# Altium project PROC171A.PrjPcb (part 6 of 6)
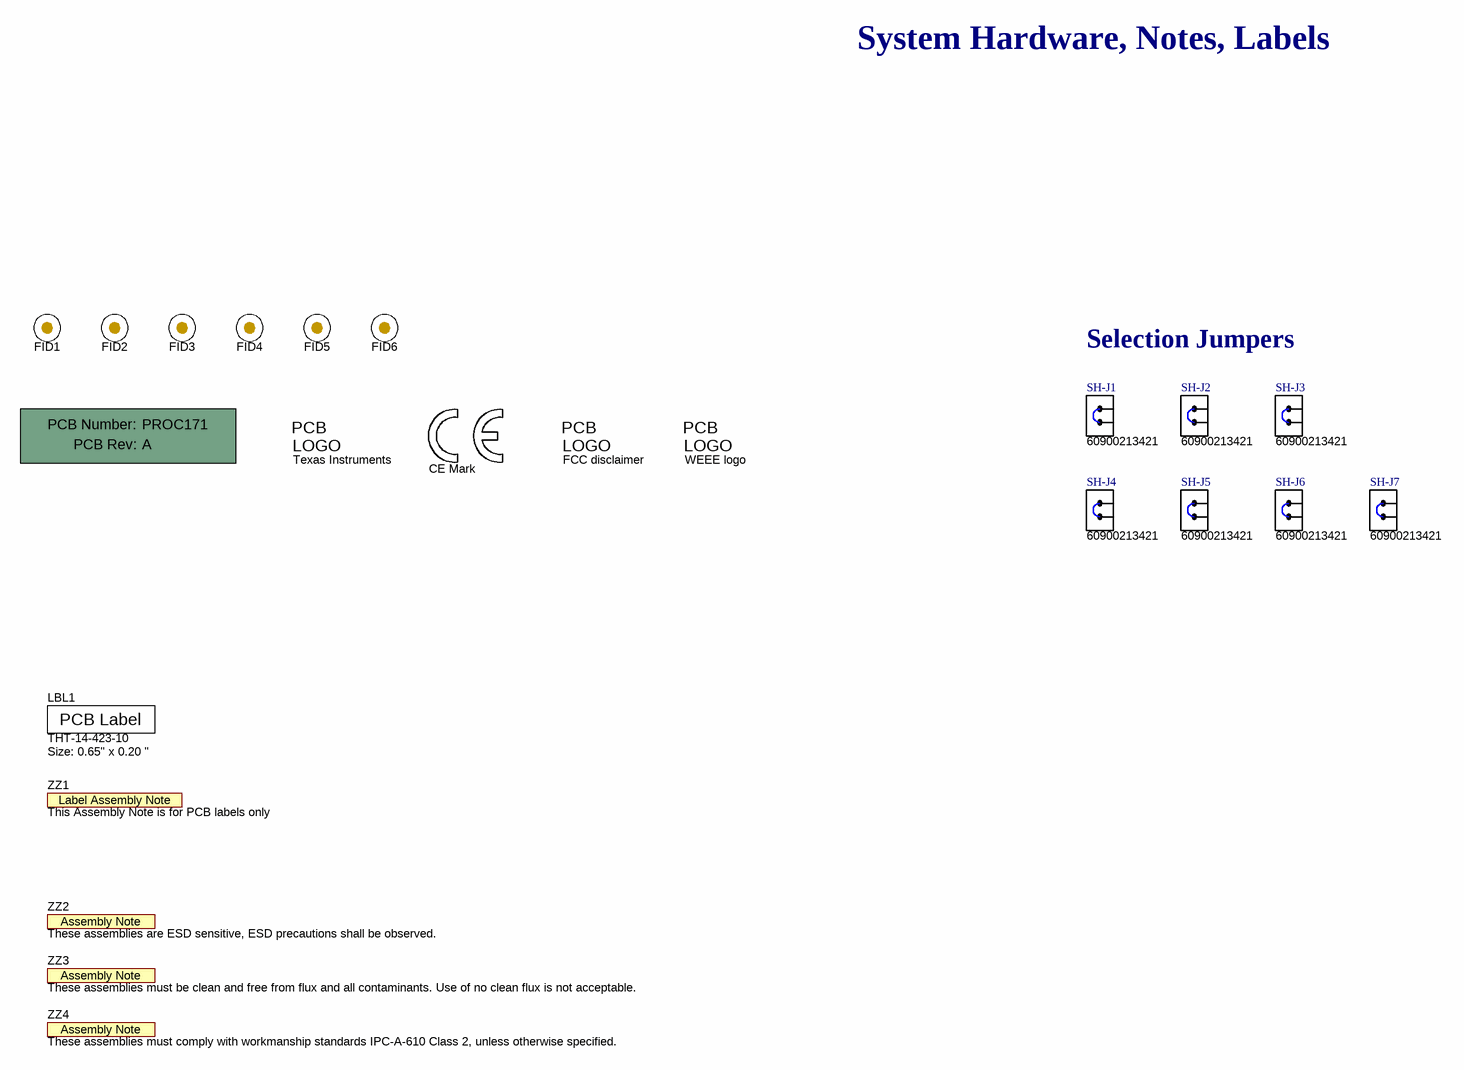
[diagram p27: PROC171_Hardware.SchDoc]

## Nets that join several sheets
GND: PROC171_System_Power_1 (34 pins), PROC171_System_Power_2 (52 pins), PROC171_AM263P_1_Power (148 pins), PROC171_AM263P_2_Clock_Reset_Boot_JTAG (30 pins), PROC171_AM263P_3_OSPI_MMC (30 pins), PROC171_AM263P_4_EMMC (17 pins), PROC171_AM263P_5_ADC_DAC (45 pins), PROC171_AM263P_6_ePWM_eQEP_FSI (6 pins), PROC171_AM263P_7_RGMII_MII (C100.1 U17.3), PROC171_AM263P_8_PRU (11 pins), PROC171_Push_Buttons (13 pins), PROC171_Test_Automation (26 pins), PROC171_Ehernet_PHY_1 (43 pins), PROC171_Ehernet_PHY_2 (37 pins), PROC171_Ehernet_RJ45_1 (10 pins), PROC171_XDS110_2 (7 pins), PROC171_Ehernet_RJ45_2 (10 pins), PROC171_Boosterpack_Headers (13 pins), PROC171_Breakout_Headers (31 pins), PROC171_IO_EXPANDER (5 pins), PROC171_LED (14 pins)
GND_XDS: PROC171_Test_Automation (7 pins), PROC171_XDS110_2 (44 pins), PROC171_XDS110_1 (14 pins)
VBUS_XDS_5V0: PROC171_XDS110_2 (R132.2 R136.2), PROC171_XDS110_1 (7 pins)
VDD_AM263P_1V2: PROC171_System_Power_2 (7 pins), PROC171_AM263P_1_Power (49 pins)
VDD_ETH_1V1: PROC171_System_Power_2 (6 pins), PROC171_Ehernet_PHY_1 (FB3.1), PROC171_Ehernet_PHY_2 (FB5.1)
VDD_ETH_2V5: PROC171_System_Power_2 (6 pins), PROC171_Ehernet_PHY_1 (FB4.1), PROC171_Ehernet_PHY_2 (FB6.1)
VDD_XDS3V3: PROC171_Test_Automation (13 pins), PROC171_XDS110_2 (38 pins), PROC171_XDS110_1 (7 pins)
VDDA_AM263P_1V8_LDO: PROC171_AM263P_1_Power (10 pins), PROC171_AM263P_5_ADC_DAC (S1.1)
VPP_AM263P_1V7: PROC171_System_Power_2 (5 pins), PROC171_AM263P_1_Power (R190.2 R360.2)
VSYS_3V3: PROC171_System_Power_1 (J12.1), PROC171_System_Power_2 (14 pins), PROC171_AM263P_1_Power (19 pins), PROC171_AM263P_2_Clock_Reset_Boot_JTAG (14 pins), PROC171_AM263P_Serial_Connectivity (R175.2 R176.2), PROC171_AM263P_3_OSPI_MMC (38 pins), PROC171_AM263P_4_EMMC (15 pins), PROC171_AM263P_6_ePWM_eQEP_FSI (7 pins), PROC171_AM263P_7_RGMII_MII (C100.2 R63.2 R64.2 U17.8), PROC171_AM263P_8_PRU (14 pins), PROC171_Push_Buttons (8 pins), PROC171_Test_Automation (U57.1), PROC171_Ehernet_PHY_1 (30 pins), PROC171_Ehernet_PHY_2 (22 pins), PROC171_Ehernet_RJ45_1 (R224.1 R226.2 R228.2), PROC171_XDS110_2 (6 pins), PROC171_Ehernet_RJ45_2 (R230.1 R232.2 R234.2), PROC171_Boosterpack_Headers (12 pins), PROC171_Breakout_Headers (8 pins), PROC171_IO_EXPANDER (6 pins), PROC171_LED (17 pins)
VSYS_5V0: PROC171_System_Power_1 (5 pins), PROC171_System_Power_2 (23 pins), PROC171_AM263P_1_Power (R1.2), PROC171_Breakout_Headers (16 pins), PROC171_LED (R257.2 R265.2 R302.2)
VSYS_TA_3V3: PROC171_AM263P_2_Clock_Reset_Boot_JTAG (12 pins), PROC171_Test_Automation (26 pins), PROC171_LED (R315.2)
VUSB_5V0: PROC171_System_Power_1 (20 pins), PROC171_Test_Automation (C187.2 C188.1 R193.2 U36.2), PROC171_Boosterpack_Headers (J10.1 J14.1)
ADC_EXT_VREF: PROC171_AM263P_5_ADC_DAC (S2.3 S2.6), PROC171_Breakout_Headers (J17.2)
AM263P_ADC0_AIN0: PROC171_AM263P_5_ADC_DAC (C72.1 U1.V15 U12.1 U12.10), PROC171_Boosterpack_Headers (J1/J3.23)
AM263P_ADC0_AIN1: PROC171_AM263P_5_ADC_DAC (C82.1 U1.U15 U13.2 U13.9), PROC171_Boosterpack_Headers (J1/J3.28)
AM263P_ADC0_AIN2: PROC171_AM263P_5_ADC_DAC (U1.T14), PROC171_Boosterpack_Headers (U52.32)
AM263P_ADC0_AIN2_LIN1_TXD: PROC171_AM263P_5_ADC_DAC (C88.1 U14.5 U14.6), PROC171_Boosterpack_Headers (J5/J7.66 U52.7)
AM263P_ADC0_AIN3: PROC171_AM263P_5_ADC_DAC (C84.1 U1.U14 U13.5 U13.6), PROC171_Boosterpack_Headers (J1/J3.2)
AM263P_ADC1_AIN0: PROC171_AM263P_5_ADC_DAC (C73.1 U1.T11 U12.2 U12.9), PROC171_Boosterpack_Headers (J1/J3.24)
AM263P_ADC1_AIN1: PROC171_AM263P_5_ADC_DAC (C83.1 U1.U11 U13.4 U13.7), PROC171_Boosterpack_Headers (J1/J3.29)
AM263P_ADC1_AIN2: PROC171_AM263P_5_ADC_DAC (U1.T12), PROC171_Boosterpack_Headers (U52.29)
AM263P_ADC1_AIN2_SDFM0_D2: PROC171_AM263P_5_ADC_DAC (C92.1 U15.1 U15.10), PROC171_Boosterpack_Headers (J5/J7.67 U52.11)
AM263P_ADC1_AIN3: PROC171_AM263P_5_ADC_DAC (C97.1 D16.1 U1.V12), PROC171_Boosterpack_Headers (J1/J3.6)
AM263P_ADC2_AIN0: PROC171_AM263P_5_ADC_DAC (C74.1 U1.R10 U12.4 U12.7), PROC171_Boosterpack_Headers (J1/J3.25)
AM263P_ADC2_AIN1: PROC171_AM263P_5_ADC_DAC (U1.T10), PROC171_Boosterpack_Headers (U52.38)
AM263P_ADC2_AIN1_MCAN5_RX: PROC171_AM263P_5_ADC_DAC (C85.1 U14.1 U14.10), PROC171_Boosterpack_Headers (J5/J7.63 U52.4)
AM263P_ADC2_AIN2: PROC171_AM263P_5_ADC_DAC (U1.U10), PROC171_Boosterpack_Headers (U52.27)
AM263P_ADC2_AIN2_SDFM0_CLK2: PROC171_AM263P_5_ADC_DAC (C93.1 U15.2 U15.9), PROC171_Boosterpack_Headers (J5/J7.68 U52.12)
AM263P_ADC2_AIN3: PROC171_AM263P_5_ADC_DAC (C95.1 U1.T9 U15.5 U15.6), PROC171_Boosterpack_Headers (J5/J7.42)
AM263P_ADC3_AIN0: PROC171_AM263P_5_ADC_DAC (C75.1 U1.U7 U12.5 U12.6), PROC171_Boosterpack_Headers (J1/J3.26)
AM263P_ADC3_AIN1: PROC171_AM263P_5_ADC_DAC (U1.U8), PROC171_Boosterpack_Headers (U52.36)
AM263P_ADC3_AIN1_MCAN5_TX: PROC171_AM263P_5_ADC_DAC (C86.1 U14.2 U14.9), PROC171_Boosterpack_Headers (J5/J7.64 U52.5)
AM263P_ADC3_AIN2: PROC171_AM263P_5_ADC_DAC (U1.T7), PROC171_Boosterpack_Headers (U52.25)
AM263P_ADC3_AIN2_SDFM0_D3: PROC171_AM263P_5_ADC_DAC (C94.1 U15.4 U15.7), PROC171_Boosterpack_Headers (J5/J7.69 U52.13)
AM263P_ADC3_AIN3: PROC171_AM263P_5_ADC_DAC (C96.1 D15.2 U1.R7), PROC171_Boosterpack_Headers (J5/J7.46)
AM263P_ADC4_AIN0: PROC171_AM263P_5_ADC_DAC (C81.1 U1.U6 U13.1 U13.10), PROC171_Boosterpack_Headers (J1/J3.27)
AM263P_ADC4_AIN1: PROC171_AM263P_5_ADC_DAC (U1.V5), PROC171_Boosterpack_Headers (U52.34)
AM263P_ADC4_AIN1_LIN1_RXD: PROC171_AM263P_5_ADC_DAC (C87.1 U14.4 U14.7), PROC171_Boosterpack_Headers (J5/J7.65 U52.6)
AM263P_BP_MUX_SEL: PROC171_Boosterpack_Headers (R298.2 R300.2 U51.1), PROC171_IO_EXPANDER (U63.7)
AM263P_CLKOUT0: PROC171_AM263P_2_Clock_Reset_Boot_JTAG (R4.2 TP1.1), PROC171_Ehernet_PHY_1 (R118.1)
AM263P_DAC_OUT1: PROC171_AM263P_5_ADC_DAC (R45.1), PROC171_Boosterpack_Headers (J1/J3.30)
AM263P_DAC_OUT2: PROC171_AM263P_5_ADC_DAC (R3.1), PROC171_Boosterpack_Headers (U52.23)
AM263P_EMMC0_CLK_MUX: PROC171_AM263P_3_OSPI_MMC (U53.40), PROC171_AM263P_4_EMMC (U61.M6)
AM263P_EMMC0_CMD_MUX: PROC171_AM263P_3_OSPI_MMC (U53.37), PROC171_AM263P_4_EMMC (U61.M5)
AM263P_EMMC0_D0_MUX: PROC171_AM263P_3_OSPI_MMC (U53.35), PROC171_AM263P_4_EMMC (R429.2)
AM263P_EMMC0_D1_MUX: PROC171_AM263P_3_OSPI_MMC (U53.33), PROC171_AM263P_4_EMMC (R430.2)
AM263P_EMMC0_D2_MUX: PROC171_AM263P_3_OSPI_MMC (U53.31), PROC171_AM263P_4_EMMC (R431.2)
AM263P_EMMC0_D3_MUX: PROC171_AM263P_3_OSPI_MMC (U53.28), PROC171_AM263P_4_EMMC (R432.2)
AM263P_EPWM0_A: PROC171_AM263P_6_ePWM_eQEP_FSI (R46.1), PROC171_Boosterpack_Headers (J2/J4.11)
AM263P_EPWM0_B: PROC171_AM263P_6_ePWM_eQEP_FSI (R47.1), PROC171_Boosterpack_Headers (J6/J8.59)
AM263P_EPWM1_A: PROC171_AM263P_6_ePWM_eQEP_FSI (R48.1), PROC171_Boosterpack_Headers (J2/J4.37)
AM263P_EPWM1_B: PROC171_AM263P_6_ePWM_eQEP_FSI (R49.1), PROC171_Boosterpack_Headers (J2/J4.38)
AM263P_EPWM2_A: PROC171_AM263P_6_ePWM_eQEP_FSI (R50.1), PROC171_Boosterpack_Headers (J2/J4.39)
AM263P_EPWM2_B: PROC171_AM263P_6_ePWM_eQEP_FSI (R51.1), PROC171_Boosterpack_Headers (J2/J4.40)
AM263P_EPWM3_A: PROC171_AM263P_6_ePWM_eQEP_FSI (R52.1), PROC171_Boosterpack_Headers (J6/J8.77)
AM263P_EPWM3_B: PROC171_AM263P_6_ePWM_eQEP_FSI (R53.1), PROC171_Boosterpack_Headers (J6/J8.78)
AM263P_EPWM4_A: PROC171_AM263P_6_ePWM_eQEP_FSI (R433.1), PROC171_Boosterpack_Headers (J6/J8.52)
AM263P_EPWM7_B: PROC171_AM263P_6_ePWM_eQEP_FSI (R436.1), PROC171_Boosterpack_Headers (J6/J8.51)
AM263P_EPWM9_A: PROC171_AM263P_6_ePWM_eQEP_FSI (R9.1), PROC171_Boosterpack_Headers (J6/J8.75)
AM263P_EPWM9_B: PROC171_AM263P_6_ePWM_eQEP_FSI (R12.1), PROC171_Boosterpack_Headers (J6/J8.76)
AM263P_EPWM12_A: PROC171_AM263P_6_ePWM_eQEP_FSI (R280.1), PROC171_Boosterpack_Headers (J6/J8.53)
AM263P_EPWM12_B: PROC171_AM263P_6_ePWM_eQEP_FSI (R281.1), PROC171_Boosterpack_Headers (J6/J8.57)
AM263P_EPWM13_A: PROC171_AM263P_6_ePWM_eQEP_FSI (R59.1), PROC171_Boosterpack_Headers (J6/J8.79)
AM263P_EPWM13_B: PROC171_AM263P_6_ePWM_eQEP_FSI (R60.1), PROC171_Boosterpack_Headers (J6/J8.80)
AM263P_EPWM14_A: PROC171_AM263P_6_ePWM_eQEP_FSI (R282.1), PROC171_Boosterpack_Headers (J2/J4.35)
AM263P_EPWM14_B: PROC171_AM263P_6_ePWM_eQEP_FSI (R283.1), PROC171_Boosterpack_Headers (J2/J4.36)
AM263P_EPWM15_A_BP: PROC171_AM263P_6_ePWM_eQEP_FSI (U54.3), PROC171_Boosterpack_Headers (J2/J4.34)
AM263P_EPWM15_B_BP: PROC171_AM263P_6_ePWM_eQEP_FSI (U54.6), PROC171_Boosterpack_Headers (J5/J7.45)
AM263P_EQEP0_A: PROC171_AM263P_6_ePWM_eQEP_FSI (U1.B14), PROC171_Breakout_Headers (R328.1)
AM263P_EQEP0_B: PROC171_AM263P_6_ePWM_eQEP_FSI (U1.A14), PROC171_Breakout_Headers (R329.1)
AM263P_EQEP0_INDEX: PROC171_AM263P_6_ePWM_eQEP_FSI (U1.D11), PROC171_Breakout_Headers (R330.1)
AM263P_EQEP0_STROBE: PROC171_AM263P_6_ePWM_eQEP_FSI (U1.C12), PROC171_Breakout_Headers (R331.1)
AM263P_EQEP2_A: PROC171_AM263P_Serial_Connectivity (U1.B13), PROC171_Breakout_Headers (R332.1)
AM263P_EQEP2_B: PROC171_AM263P_Serial_Connectivity (U1.A13), PROC171_Breakout_Headers (R333.1)
AM263P_EQEP2_INDEX: PROC171_AM263P_Serial_Connectivity (U1.A12), PROC171_Breakout_Headers (R334.1)
AM263P_EQEP2_STROBE: PROC171_AM263P_Serial_Connectivity (U1.B12), PROC171_Breakout_Headers (R335.1)
AM263P_FSIRX1_CLK: PROC171_AM263P_6_ePWM_eQEP_FSI (U1.E1), PROC171_Breakout_Headers (J23.1)
AM263P_FSIRX1_DATA0: PROC171_AM263P_6_ePWM_eQEP_FSI (U1.F3), PROC171_Breakout_Headers (J23.5)
AM263P_FSIRX1_DATA1: PROC171_AM263P_6_ePWM_eQEP_FSI (U1.F4), PROC171_Breakout_Headers (J23.7)
AM263P_FSITX1_CLK: PROC171_AM263P_6_ePWM_eQEP_FSI (R54.1), PROC171_Breakout_Headers (J23.2)
AM263P_FSITX1_DATA0: PROC171_AM263P_6_ePWM_eQEP_FSI (R57.1), PROC171_Breakout_Headers (J23.6)
AM263P_FSITX1_DATA1: PROC171_AM263P_6_ePWM_eQEP_FSI (R58.1), PROC171_Breakout_Headers (J23.8)
AM263P_I2C1_SCL: PROC171_AM263P_2_Clock_Reset_Boot_JTAG (U16.6), PROC171_AM263P_Serial_Connectivity (R175.1 U1.D7), PROC171_Test_Automation (U57.3), PROC171_Boosterpack_Headers (J5/J7.49), PROC171_IO_EXPANDER (U63.19), PROC171_LED (U48.15)
AM263P_I2C1_SDA: PROC171_AM263P_2_Clock_Reset_Boot_JTAG (U16.5), PROC171_AM263P_Serial_Connectivity (R176.1 U1.C8), PROC171_Test_Automation (U57.2), PROC171_Boosterpack_Headers (J5/J7.50), PROC171_IO_EXPANDER (U63.20), PROC171_LED (U48.2)
AM263P_I2C3_SCL: PROC171_AM263P_6_ePWM_eQEP_FSI (R55.1 U1.H2), PROC171_Boosterpack_Headers (J1/J3.9)
AM263P_I2C3_SDA: PROC171_AM263P_6_ePWM_eQEP_FSI (R56.1 U1.G3), PROC171_Boosterpack_Headers (J1/J3.10)
AM263P_ICSSM_MII0_COL: PROC171_AM263P_8_PRU (U49.11), PROC171_Ehernet_PHY_2 (R207.1 R219.2 U37.45), PROC171_Ehernet_RJ45_2 (R231.2)
AM263P_ICSSM_MII0_RXCLK: PROC171_AM263P_8_PRU (U23.32), PROC171_Ehernet_PHY_2 (R196.1)
AM263P_ICSSM_MII0_RXD0: PROC171_AM263P_8_PRU (U23.41), PROC171_Ehernet_PHY_2 (R198.1 R203.1 R215.2)
AM263P_ICSSM_MII0_RXD1: PROC171_AM263P_8_PRU (U23.39), PROC171_Ehernet_PHY_2 (R199.1 R204.1 R216.2)
AM263P_ICSSM_MII0_RXD2: PROC171_AM263P_8_PRU (U23.38), PROC171_Ehernet_PHY_2 (R200.1 R210.1 R222.2)
AM263P_ICSSM_MII0_RXD3: PROC171_AM263P_8_PRU (U23.36), PROC171_Ehernet_PHY_2 (R201.1 R211.1 R223.2)
AM263P_ICSSM_MII0_RXDV: PROC171_AM263P_8_PRU (U23.34), PROC171_Ehernet_PHY_2 (R197.1 R205.1 R217.2)
AM263P_ICSSM_MII0_RXER: PROC171_AM263P_8_PRU (U49.2), PROC171_Ehernet_PHY_2 (R206.1 R218.2 U37.46), PROC171_Ehernet_RJ45_2 (R235.2)
AM263P_ICSSM_MII0_RXLINK: PROC171_AM263P_8_PRU (U49.5), PROC171_Ehernet_PHY_2 (R208.1 R220.2 U37.47), PROC171_Ehernet_RJ45_2 (R233.2)
AM263P_ICSSM_MII0_TXCLK: PROC171_AM263P_8_PRU (U23.19), PROC171_Ehernet_PHY_2 (U37.29)
AM263P_ICSSM_MII0_TXD0: PROC171_AM263P_8_PRU (U23.29), PROC171_Ehernet_PHY_2 (U37.28)
AM263P_ICSSM_MII0_TXD1: PROC171_AM263P_8_PRU (U23.27), PROC171_Ehernet_PHY_2 (U37.27)
AM263P_ICSSM_MII0_TXD2: PROC171_AM263P_8_PRU (U23.25), PROC171_Ehernet_PHY_2 (U37.26)
AM263P_ICSSM_MII0_TXD3: PROC171_AM263P_8_PRU (U23.23), PROC171_Ehernet_PHY_2 (U37.25)
AM263P_ICSSM_MII0_TXEN: PROC171_AM263P_8_PRU (U23.21), PROC171_Ehernet_PHY_2 (U37.37)
AM263P_ICSSM_MII1_COL: PROC171_AM263P_8_PRU (U1.C18), PROC171_Ehernet_PHY_1 (R112.1 R124.2 U22.45), PROC171_Ehernet_RJ45_1 (R225.2)
AM263P_ICSSM_MII1_RXCLK: PROC171_AM263P_8_PRU (U1.E16), PROC171_Ehernet_PHY_1 (U50.31)
AM263P_ICSSM_MII1_RXD0: PROC171_AM263P_8_PRU (U1.F18), PROC171_Ehernet_PHY_1 (U50.42)
AM263P_ICSSM_MII1_RXD1: PROC171_AM263P_8_PRU (U1.G16), PROC171_Ehernet_PHY_1 (U50.40)
AM263P_ICSSM_MII1_RXD2: PROC171_AM263P_8_PRU (U1.E17), PROC171_Ehernet_PHY_1 (U50.37)
AM263P_ICSSM_MII1_RXD3: PROC171_AM263P_8_PRU (U1.E18), PROC171_Ehernet_PHY_1 (U50.35)
AM263P_ICSSM_MII1_RXDV: PROC171_AM263P_8_PRU (U1.F16), PROC171_Ehernet_PHY_1 (U50.33)
AM263P_ICSSM_MII1_RXER: PROC171_AM263P_8_PRU (U1.F15), PROC171_Ehernet_PHY_1 (R111.1 R123.2 U22.46), PROC171_Ehernet_RJ45_1 (R229.2)
AM263P_ICSSM_MII1_RXLINK: PROC171_AM263P_8_PRU (U1.D18), PROC171_Ehernet_PHY_1 (R110.1 R122.2 U22.47), PROC171_Ehernet_RJ45_1 (R227.2)
AM263P_ICSSM_MII1_TXCLK: PROC171_AM263P_8_PRU (R86.1), PROC171_Ehernet_PHY_1 (U50.18)
AM263P_ICSSM_MII1_TXD0: PROC171_AM263P_8_PRU (R81.1), PROC171_Ehernet_PHY_1 (U50.28)
AM263P_ICSSM_MII1_TXD1: PROC171_AM263P_8_PRU (R82.1), PROC171_Ehernet_PHY_1 (U50.26)
AM263P_ICSSM_MII1_TXD2: PROC171_AM263P_8_PRU (R83.1), PROC171_Ehernet_PHY_1 (U50.24)
AM263P_ICSSM_MII1_TXD3: PROC171_AM263P_8_PRU (R84.1), PROC171_Ehernet_PHY_1 (U50.22)
AM263P_ICSSM_MII1_TXEN: PROC171_AM263P_8_PRU (R85.1), PROC171_Ehernet_PHY_1 (U50.20)
AM263P_IEP0_EDC_SYNC_OUT0: PROC171_AM263P_8_PRU (R88.1), PROC171_Boosterpack_Headers (J6/J8.72)
AM263P_IEP0_EDIO_DATA_IN_OUT31: PROC171_AM263P_8_PRU (R87.1), PROC171_Boosterpack_Headers (J6/J8.71)
AM263P_INT1_PB_GPIO123: PROC171_AM263P_9_SDFM (U1.D14), PROC171_Push_Buttons (U34.4)
AM263P_LED_DRIVER_EN: PROC171_IO_EXPANDER (U63.5), PROC171_LED (R278.2 U48.8)
AM263P_LED_EN: PROC171_IO_EXPANDER (U63.6), PROC171_LED (R303.1 R304.2)
AM263P_LIN1_RXD: PROC171_AM263P_Serial_Connectivity (U1.A9), PROC171_Boosterpack_Headers (U52.33)
AM263P_LIN1_TXD: PROC171_AM263P_Serial_Connectivity (R297.1), PROC171_Boosterpack_Headers (U52.31)
AM263P_LIN2_RXD: PROC171_AM263P_Serial_Connectivity (U1.B8), PROC171_Boosterpack_Headers (U52.41)
AM263P_LIN2_TXD: PROC171_AM263P_Serial_Connectivity (R166.1), PROC171_Boosterpack_Headers (U52.39)
AM263P_MCAN3_RX: PROC171_AM263P_Serial_Connectivity (U1.B7), PROC171_Breakout_Headers (R249.1)
AM263P_MCAN3_TX: PROC171_AM263P_Serial_Connectivity (R401.1), PROC171_Breakout_Headers (U42.1)
AM263P_MCAN5_RX: PROC171_AM263P_6_ePWM_eQEP_FSI (U1.G4), PROC171_Boosterpack_Headers (U52.37)
AM263P_MCAN5_TX: PROC171_AM263P_6_ePWM_eQEP_FSI (R393.1), PROC171_Boosterpack_Headers (U52.35)
AM263P_MCAN_STB: PROC171_Breakout_Headers (R248.2), PROC171_IO_EXPANDER (U63.12)
AM263P_MMC_MUX_EN: PROC171_AM263P_3_OSPI_MMC (R390.2 R392.2 U53.8), PROC171_IO_EXPANDER (U63.11)
AM263P_MMC_MUX_SEL: PROC171_AM263P_3_OSPI_MMC (R389.2 R391.2 U53.9 U53.10), PROC171_IO_EXPANDER (U63.10)
AM263P_OSPI0_D4: PROC171_AM263P_Serial_Connectivity (R403.1), PROC171_AM263P_3_OSPI_MMC (R361.1 R370.2)
AM263P_OSPI0_D5: PROC171_AM263P_Serial_Connectivity (R167.1), PROC171_AM263P_3_OSPI_MMC (R365.1 R369.2)
AM263P_OSPI0_D6: PROC171_AM263P_Serial_Connectivity (R404.1), PROC171_AM263P_3_OSPI_MMC (R366.1 R368.2)
AM263P_OSPI0_D7: PROC171_AM263P_Serial_Connectivity (R168.1), PROC171_AM263P_3_OSPI_MMC (R367.2 R376.1)
AM263P_OSPI0_DQS: PROC171_AM263P_Serial_Connectivity (R165.1), PROC171_AM263P_3_OSPI_MMC (R381.1)
AM263P_OSPI0_LBCLK: PROC171_AM263P_Serial_Connectivity (R402.1), PROC171_AM263P_3_OSPI_MMC (R382.1)
AM263P_OSPI0_RST: PROC171_AM263P_3_OSPI_MMC (R387.1 U35.1), PROC171_AM263P_6_ePWM_eQEP_FSI (R99.1)
AM263P_OSPI_ECS: PROC171_AM263P_3_OSPI_MMC (R435.1 U7.A5), PROC171_AM263P_6_ePWM_eQEP_FSI (R13.1)
AM263P_PORZ_PB: PROC171_AM263P_2_Clock_Reset_Boot_JTAG (U2.1), PROC171_Push_Buttons (U34.6)
AM263P_PR0_MDIO0_MDC: PROC171_AM263P_7_RGMII_MII (U17.2), PROC171_AM263P_8_PRU (R71.1 R73.1)
AM263P_PR0_MDIO0_MDIO: PROC171_AM263P_7_RGMII_MII (U17.4), PROC171_AM263P_8_PRU (R72.1 R74.1)
AM263P_PRU/BP_MUX_EN: PROC171_AM263P_8_PRU (R288.2 R290.2 U23.8 U46.2), PROC171_Boosterpack_Headers (U52.8), PROC171_IO_EXPANDER (U63.15)
AM263P_PRU_MUX_SEL: PROC171_AM263P_8_PRU (5 pins), PROC171_IO_EXPANDER (U63.8)
AM263P_RESETN_PB: PROC171_AM263P_2_Clock_Reset_Boot_JTAG (R5.1), PROC171_Push_Buttons (R179.1 U33.4)
AM263P_RGMII1_RD0: PROC171_AM263P_7_RGMII_MII (U1.U17), PROC171_Ehernet_PHY_1 (U50.41)
AM263P_RGMII1_RD1: PROC171_AM263P_7_RGMII_MII (U1.T17), PROC171_Ehernet_PHY_1 (U50.39)
AM263P_RGMII1_RD2: PROC171_AM263P_7_RGMII_MII (U1.U18), PROC171_Ehernet_PHY_1 (U50.38)
AM263P_RGMII1_RD3: PROC171_AM263P_7_RGMII_MII (U1.T18), PROC171_Ehernet_PHY_1 (U50.36)
AM263P_RGMII1_RX_CTL: PROC171_AM263P_7_RGMII_MII (U1.R18), PROC171_Ehernet_PHY_1 (U50.34)
AM263P_RGMII1_RXC: PROC171_AM263P_7_RGMII_MII (U1.R17), PROC171_Ehernet_PHY_1 (U50.32)
AM263P_RGMII1_TD0: PROC171_AM263P_7_RGMII_MII (R65.1), PROC171_Ehernet_PHY_1 (U50.29)
AM263P_RGMII1_TD1: PROC171_AM263P_7_RGMII_MII (R66.1), PROC171_Ehernet_PHY_1 (U50.27)
AM263P_RGMII1_TD2: PROC171_AM263P_7_RGMII_MII (R67.1), PROC171_Ehernet_PHY_1 (U50.25)
AM263P_RGMII1_TD3: PROC171_AM263P_7_RGMII_MII (R68.1), PROC171_Ehernet_PHY_1 (U50.23)
AM263P_RGMII1_TX_CTL: PROC171_AM263P_7_RGMII_MII (R69.1), PROC171_Ehernet_PHY_1 (U50.21)
AM263P_RGMII1_TXC: PROC171_AM263P_7_RGMII_MII (R70.1), PROC171_Ehernet_PHY_1 (U50.19)
AM263P_SAFETY_ERRORN: PROC171_AM263P_2_Clock_Reset_Boot_JTAG (R258.1 U1.D4), PROC171_LED (R268.1 R272.1)
AM263P_SD_ENABLE_GPIO122: PROC171_AM263P_3_OSPI_MMC (U9.2), PROC171_AM263P_9_SDFM (U1.B16)
AM263P_SDFM0_CLK1: PROC171_AM263P_9_SDFM (U1.A16), PROC171_Boosterpack_Headers (J6/J8.74)
AM263P_SDFM0_CLK2: PROC171_AM263P_9_SDFM (U1.B15), PROC171_Boosterpack_Headers (U52.26)
AM263P_SDFM0_CLK3: PROC171_AM263P_9_SDFM (U1.A15), PROC171_Boosterpack_Headers (U52.22)
AM263P_SDFM0_D2: PROC171_AM263P_9_SDFM (U1.C13), PROC171_Boosterpack_Headers (U52.28)
AM263P_SDFM0_D3: PROC171_AM263P_9_SDFM (U1.C14), PROC171_Boosterpack_Headers (U52.24)
AM263P_SFDM0_D1: PROC171_AM263P_9_SDFM (U1.D13), PROC171_Boosterpack_Headers (J6/J8.73)
AM263P_SOP0: PROC171_AM263P_2_Clock_Reset_Boot_JTAG (U4.15), PROC171_AM263P_3_OSPI_MMC (R42.2)
AM263P_SOP1: PROC171_AM263P_2_Clock_Reset_Boot_JTAG (U4.14), PROC171_AM263P_3_OSPI_MMC (R43.2)
AM263P_SOP2: PROC171_AM263P_2_Clock_Reset_Boot_JTAG (U4.13), PROC171_AM263P_Serial_Connectivity (R173.2)
AM263P_SOP3: PROC171_AM263P_2_Clock_Reset_Boot_JTAG (U4.12), PROC171_AM263P_Serial_Connectivity (R174.2)
AM263P_SPI0_CLK: PROC171_AM263P_Serial_Connectivity (R169.1 R173.1), PROC171_Boosterpack_Headers (U51.2)
AM263P_SPI0_CS0: PROC171_AM263P_Serial_Connectivity (U1.C11), PROC171_Boosterpack_Headers (U51.14)
AM263P_SPI0_D0: PROC171_AM263P_Serial_Connectivity (R170.1 R174.1), PROC171_Boosterpack_Headers (U51.11)
AM263P_SPI0_D1: PROC171_AM263P_Serial_Connectivity (U1.B11), PROC171_Boosterpack_Headers (U51.5)
AM263P_SPI1_CLK: PROC171_AM263P_Serial_Connectivity (R171.1), PROC171_Boosterpack_Headers (J5/J7.47)
AM263P_SPI1_CS0: PROC171_AM263P_Serial_Connectivity (U1.C9), PROC171_Boosterpack_Headers (J6/J8.58)
AM263P_SPI1_D0: PROC171_AM263P_Serial_Connectivity (R172.1), PROC171_Boosterpack_Headers (J6/J8.55)
AM263P_SPI1_D1: PROC171_AM263P_Serial_Connectivity (U1.D9), PROC171_Boosterpack_Headers (J6/J8.54)
AM263P_TCK: PROC171_AM263P_2_Clock_Reset_Boot_JTAG (U1.B3), PROC171_XDS110_2 (R324.1)
AM263P_TDI: PROC171_AM263P_2_Clock_Reset_Boot_JTAG (U1.C5), PROC171_XDS110_2 (R326.1)
AM263P_TDO: PROC171_AM263P_2_Clock_Reset_Boot_JTAG (R7.1), PROC171_XDS110_2 (U26.3)
AM263P_TMS: PROC171_AM263P_2_Clock_Reset_Boot_JTAG (U1.D5), PROC171_XDS110_2 (R325.1)
AM263P_U52_MUX_SEL: PROC171_Boosterpack_Headers (R441.2 R442.2 U52.9 U52.10), PROC171_IO_EXPANDER (U63.16)
AM263P_UART0_RXD: PROC171_AM263P_Serial_Connectivity (U1.A7), PROC171_XDS110_2 (R327.1)
AM263P_UART0_TXD: PROC171_AM263P_Serial_Connectivity (R164.1), PROC171_XDS110_2 (U27.3)
AM263P_UART5_RXD: PROC171_AM263P_6_ePWM_eQEP_FSI (U54.5), PROC171_Boosterpack_Headers (J1/J3.3)
AM263P_UART5_TXD: PROC171_AM263P_6_ePWM_eQEP_FSI (U54.2), PROC171_Boosterpack_Headers (J1/J3.4)
AM263P_WARMRSTN: PROC171_AM263P_2_Clock_Reset_Boot_JTAG (R5.2 U1.C3), PROC171_AM263P_3_OSPI_MMC (U9.1 U35.2), PROC171_AM263P_4_EMMC (U62.2), PROC171_Ehernet_PHY_1 (U65.2), PROC171_Ehernet_PHY_2 (U60.2), PROC171_IO_EXPANDER (U63.24)
AM263P_XDS_I2C2_SDA: PROC171_Test_Automation (R413.2), PROC171_XDS110_2 (U24.81)
AM263P_XDS_I2C_SCL: PROC171_Test_Automation (R414.2), PROC171_XDS110_2 (U24.82)
BOOTMODE_XDS_I2C_SCL: PROC171_Test_Automation (U56.3), PROC171_XDS110_2 (R399.1 U24.49)
BOOTMODE_XDS_I2C_SDA: PROC171_Test_Automation (U56.2), PROC171_XDS110_2 (R400.1 U24.50)
BP_PORZ: PROC171_Push_Buttons (R180.2), PROC171_Boosterpack_Headers (J2/J4.16 J6/J8.56)
CPSW RGMI1/ICSSM_MII1_RST_EN: PROC171_Ehernet_PHY_1 (R424.2 U65.1), PROC171_IO_EXPANDER (U63.3)
CPSW RGMI2/ICSSM_MII0_RST_EN: PROC171_Ehernet_PHY_2 (R417.2 U60.1), PROC171_IO_EXPANDER (U63.4)
DAC_EXT_VREF: PROC171_AM263P_5_ADC_DAC (S1.3), PROC171_Breakout_Headers (J18.2)
EMMC_RST_EN: PROC171_AM263P_4_EMMC (R420.2 U62.1), PROC171_IO_EXPANDER (U63.2)
ETH1_CLKOUT: PROC171_Ehernet_PHY_1 (R106.2), PROC171_Ehernet_PHY_2 (R213.1)
ETH1_TD_A_N: PROC171_Ehernet_PHY_1 (U22.2), PROC171_Ehernet_RJ45_1 (J7.10 U38.2 U38.9)
ETH1_TD_A_P: PROC171_Ehernet_PHY_1 (U22.1), PROC171_Ehernet_RJ45_1 (J7.9 U38.1 U38.10)
ETH1_TD_B_N: PROC171_Ehernet_PHY_1 (U22.5), PROC171_Ehernet_RJ45_1 (J7.8 U38.5 U38.6)
ETH1_TD_B_P: PROC171_Ehernet_PHY_1 (U22.4), PROC171_Ehernet_RJ45_1 (J7.7 U38.4 U38.7)
ETH1_TD_C_N: PROC171_Ehernet_PHY_1 (U22.8), PROC171_Ehernet_RJ45_1 (J7.6 U39.2 U39.9)
ETH1_TD_C_P: PROC171_Ehernet_PHY_1 (U22.7), PROC171_Ehernet_RJ45_1 (J7.5 U39.1 U39.10)
ETH1_TD_D_N: PROC171_Ehernet_PHY_1 (U22.11), PROC171_Ehernet_RJ45_1 (J7.4 U39.5 U39.6)
ETH1_TD_D_P: PROC171_Ehernet_PHY_1 (U22.10), PROC171_Ehernet_RJ45_1 (J7.3 U39.4 U39.7)
ETH2_TD_A_N: PROC171_Ehernet_PHY_2 (U37.2), PROC171_Ehernet_RJ45_2 (J8.10 U40.2 U40.9)
ETH2_TD_A_P: PROC171_Ehernet_PHY_2 (U37.1), PROC171_Ehernet_RJ45_2 (J8.9 U40.1 U40.10)
ETH2_TD_B_N: PROC171_Ehernet_PHY_2 (U37.5), PROC171_Ehernet_RJ45_2 (J8.8 U40.5 U40.6)
ETH2_TD_B_P: PROC171_Ehernet_PHY_2 (U37.4), PROC171_Ehernet_RJ45_2 (J8.7 U40.4 U40.7)
ETH2_TD_C_N: PROC171_Ehernet_PHY_2 (U37.8), PROC171_Ehernet_RJ45_2 (J8.6 U41.2 U41.9)
ETH2_TD_C_P: PROC171_Ehernet_PHY_2 (U37.7), PROC171_Ehernet_RJ45_2 (J8.5 U41.1 U41.10)
ETH2_TD_D_N: PROC171_Ehernet_PHY_2 (U37.11), PROC171_Ehernet_RJ45_2 (J8.4 U41.5 U41.6)
ETH2_TD_D_P: PROC171_Ehernet_PHY_2 (U37.10), PROC171_Ehernet_RJ45_2 (J8.3 U41.4 U41.7)
MDIO_CLOCK: PROC171_AM263P_7_RGMII_MII (U17.10), PROC171_Ehernet_PHY_1 (U22.42), PROC171_Ehernet_PHY_2 (U37.42)
MDIO_DATA: PROC171_AM263P_7_RGMII_MII (U17.6), PROC171_Ehernet_PHY_1 (U22.41), PROC171_Ehernet_PHY_2 (U37.41)
PG_VDD_1V2: PROC171_System_Power_2 (R295.1 U29.5), PROC171_AM263P_2_Clock_Reset_Boot_JTAG (U2.3), PROC171_LED (R317.1)
PG_VSYS_3V3: PROC171_System_Power_2 (R296.1 U32.5), PROC171_AM263P_2_Clock_Reset_Boot_JTAG (U2.6)
PR0_PRU0_GPIO0_MUX: PROC171_AM263P_8_PRU (U23.42), PROC171_Boosterpack_Headers (J2/J4.33)
PR0_PRU0_GPIO1_MUX: PROC171_AM263P_8_PRU (U23.40), PROC171_Boosterpack_Headers (J2/J4.32)
PR0_PRU0_GPIO2_MUX: PROC171_AM263P_8_PRU (U23.37), PROC171_Boosterpack_Headers (J2/J4.31)
PR0_PRU0_GPIO3_MUX: PROC171_AM263P_8_PRU (U23.35), PROC171_Boosterpack_Headers (J2/J4.19)
PR0_PRU0_GPIO4_MUX: PROC171_AM263P_8_PRU (U23.33), PROC171_Boosterpack_Headers (J2/J4.17)
PR0_PRU0_GPIO5_MUX: PROC171_AM263P_8_PRU (U49.3), PROC171_Boosterpack_Headers (J2/J4.13)
PR0_PRU0_GPIO6_MUX: PROC171_AM263P_8_PRU (U23.31), PROC171_Boosterpack_Headers (J5/J7.48)
PR0_PRU0_GPIO8_MUX: PROC171_AM263P_8_PRU (U49.6), PROC171_Boosterpack_Headers (U51.13)
PR0_PRU0_GPIO9_MUX: PROC171_AM263P_8_PRU (U49.10), PROC171_Boosterpack_Headers (U52.40)
PR0_PRU0_GPIO10_MUX: PROC171_AM263P_8_PRU (U49.13), PROC171_Boosterpack_Headers (J1/J3.8)
PR0_PRU0_GPIO11_MUX: PROC171_AM263P_8_PRU (U23.28), PROC171_Boosterpack_Headers (U52.42)
PR0_PRU0_GPIO12_MUX: PROC171_AM263P_8_PRU (U23.26), PROC171_Boosterpack_Headers (J1/J3.5)
PR0_PRU0_GPIO13_MUX: PROC171_AM263P_8_PRU (U23.24), PROC171_Boosterpack_Headers (U51.10)
PR0_PRU0_GPIO14_MUX: PROC171_AM263P_8_PRU (U23.22), PROC171_Boosterpack_Headers (U51.6)
PR0_PRU0_GPIO15_MUX: PROC171_AM263P_8_PRU (U23.20), PROC171_Boosterpack_Headers (J2/J4.12)
PR0_PRU0_GPIO16_MUX: PROC171_AM263P_8_PRU (U23.18), PROC171_Boosterpack_Headers (U51.3)
PRU/BP_MUX_EN_INV: PROC171_AM263P_8_PRU (R96.2 U46.4 U49.15), PROC171_Boosterpack_Headers (U51.15)
RGMII1_ICSSM_MUX_SEL_GPIO105: PROC171_AM263P_7_RGMII_MII (U17.1 U17.5), PROC171_AM263P_8_PRU (U1.D17), PROC171_Ehernet_PHY_1 (R291.2 R293.2 U50.9 U50.10)
RJ45_1_VCC: PROC171_Ehernet_RJ45_1 (J7.2 TP21.1), PROC171_Ehernet_RJ45_2 (J8.2 TP22.1)
TA_GPIO1: PROC171_Push_Buttons (Q3.1), PROC171_Test_Automation (R185.2 R342.2 R350.1)
TA_GPIO1_XDS: PROC171_Test_Automation (R341.2 U58.2), PROC171_XDS110_2 (U24.74)
TA_GPIO2_XDS: PROC171_Test_Automation (R301.2 U59.2), PROC171_XDS110_2 (U24.73)
TA_GPIO3: PROC171_AM263P_2_Clock_Reset_Boot_JTAG (U5.1), PROC171_Test_Automation (J1.2 R183.2 R343.2 R352.1)
TA_GPIO3_XDS: PROC171_Test_Automation (R340.2 U58.3), PROC171_XDS110_2 (U24.72)
TA_GPIO4: PROC171_AM263P_2_Clock_Reset_Boot_JTAG (U3.1), PROC171_Test_Automation (R182.2 R344.2 R354.1)
TA_GPIO4_XDS: PROC171_Test_Automation (R339.2 U58.4), PROC171_XDS110_2 (U24.71)
TA_I2C_SCL: PROC171_AM263P_2_Clock_Reset_Boot_JTAG (U3.12), PROC171_Test_Automation (R191.1 R356.1 R411.2)
TA_I2C_SDA: PROC171_AM263P_2_Clock_Reset_Boot_JTAG (U3.13), PROC171_Test_Automation (R192.1 R358.1 R409.2)
TA_PORZ: PROC171_Push_Buttons (Q1.1 R180.1), PROC171_Test_Automation (R187.2 R345.2 R347.1)
TA_PORZn_XDS: PROC171_Test_Automation (R338.2 U58.5), PROC171_XDS110_2 (U24.77)
TA_POWERDOWNZ: PROC171_System_Power_1 (U47.2), PROC171_Test_Automation (R188.2 R346.1 R353.2)
TA_PWRDNz_XDS: PROC171_Test_Automation (R336.2 U58.7), PROC171_XDS110_2 (U24.78)
TA_RESETZ: PROC171_Push_Buttons (Q2.1), PROC171_Test_Automation (R186.2 R348.1 R349.2)
TA_RESETz_XDS: PROC171_Test_Automation (R337.2 TP32.1 U58.6), PROC171_XDS110_2 (U24.76)
UART/EPWM_MUX_EN: PROC171_AM263P_6_ePWM_eQEP_FSI (R396.1 R398.2 U54.15), PROC171_IO_EXPANDER (U63.14)
UART/EPWM_MUX_SEL: PROC171_AM263P_6_ePWM_eQEP_FSI (R395.1 R397.2 U54.1), PROC171_IO_EXPANDER (U63.1)
VPP_LDO_EN: PROC171_System_Power_2 (R364.2 U55.4), PROC171_IO_EXPANDER (U63.13)
XDSET_1_D_N: PROC171_XDS110_2 (U24.93), PROC171_XDS110_1 (J34.2 U44.1 U44.10)
XDSET_1_D_P: PROC171_XDS110_2 (U24.94), PROC171_XDS110_1 (J34.3 U44.2 U44.9)
XDSET_1_ID: PROC171_XDS110_2 (R130.1), PROC171_XDS110_1 (J34.4 U44.4 U44.7)

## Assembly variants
001: not fitted C89 C253 C254 C254 C255 C256 C264 C265 C266 C267 R3 R63 R63 R73 R73 R109 R110 R111 R112 R113 R114 R115 R116 R118 R120 R121 R122 R123 R124 R125 R127 R128 R130 R190 R203 R205 R206 R207 R208 R209 R210 R211 R213 R215 R216 R217 R218 R219 R220 R222 R223 R250 R261 R269 R270 R274 R287 R290 R291 R294 R298 R308 R309 R310 R320 R321 R322 R346 R347 R348 R350 R351 R352 R354 R355 R356 R357 R358 R360 R362 R363 R364 R367 R368 R369 R370 R371 R372 R372 R373 R374 R382 R382 R382 R383 R384 R385 R386 R389 R392 R396 R397 R406 R410 R412 R415 R419 R420 R421 R422 R429 R430 R431 R432 R439 R440 R442 R443 R445 R? R? U55 U61 U62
